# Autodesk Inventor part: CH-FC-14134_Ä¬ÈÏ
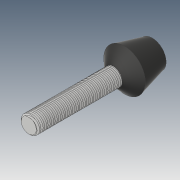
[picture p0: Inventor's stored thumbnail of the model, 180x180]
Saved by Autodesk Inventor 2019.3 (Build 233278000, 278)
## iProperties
Created: 2010-06
Part Number: CH-FC-14134_Ä¬ÈÏ
Material: Ogólny
Document SubType Name: Modeling
Designer: CADENGINEERING4
Density: 1 g/cm^3
Appearance: Domyślna
Author: CADENGINEERING4
Revision Number: ÈÎºÎ
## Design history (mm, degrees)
feature "NONE"
node "Bryła1"
